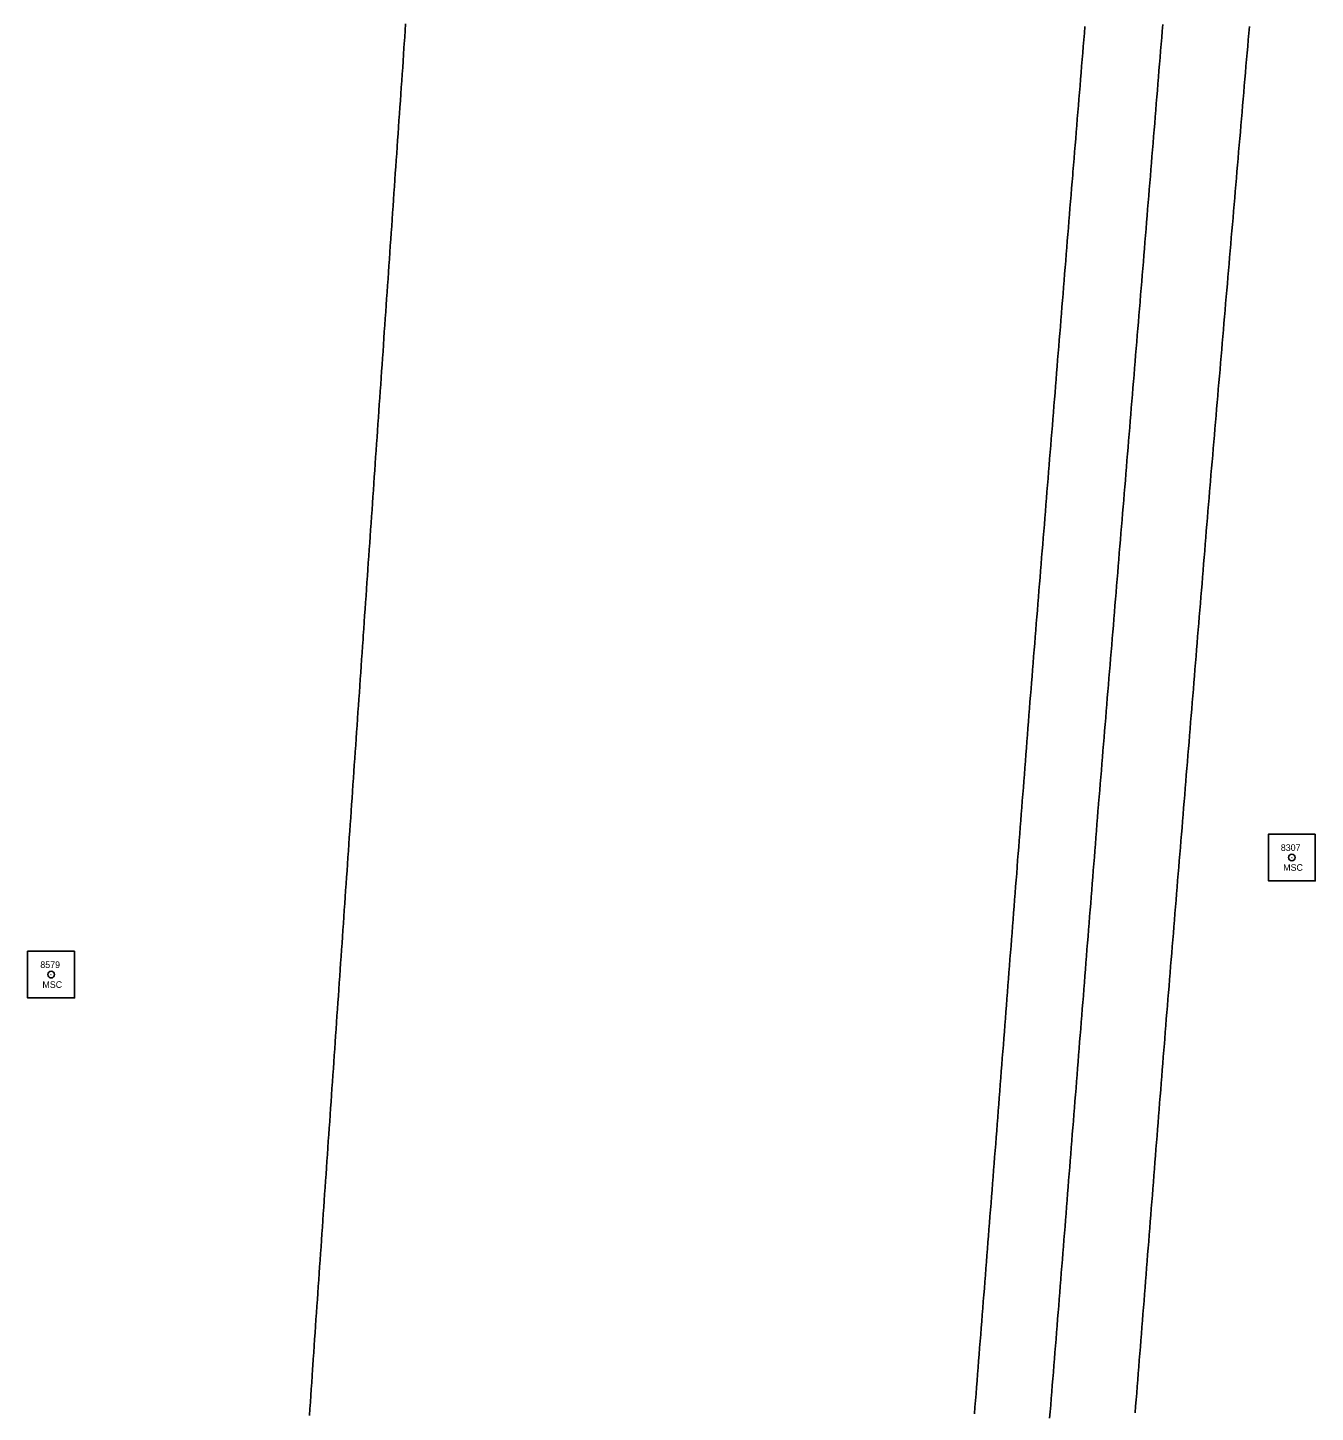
# Model space of a CAD drawing. Extents: x 205929 to 2357175, y -1785700 to 846739.
# Drawn here: x 2023477.3 to 2023671.7, y 810768.6 to 810977.7 of the extents above; entities that cross this region are included whole.
import ezdxf

# ---------------------------------------------------------------- set-up
doc = ezdxf.new("R2010")
doc.units = 0
for name, color, linetype in [('RD_HC_Survey', 7, 'Continuous'), ('RD_HC_txCode', 7, 'Continuous'), ('RD_Sketch1', 7, 'Continuous'), ('RD_SMD_Locator', 7, 'Continuous')]:
    doc.layers.add(name, color=color, linetype=linetype)

msp = doc.modelspace()

# ---------------------------------------------------------------- linework, layer by layer
at = {"layer": 'RD_HC_Survey'}
for points in [[(2023671.7, 810855.9), (2023664.63, 810855.9), (2023664.63, 810848.82), (2023671.7, 810848.82)], [(2023484.33, 810838.22), (2023477.25, 810838.22), (2023477.25, 810831.15), (2023484.33, 810831.15)]]:
    msp.add_lwpolyline(points, close=True, dxfattribs=at)
for centre in [(2023668.16, 810852.36), (2023480.79, 810834.68)]:
    msp.add_circle(centre, 0.5, dxfattribs=at)
at = {"layer": 'RD_Sketch1'}
for points in [[(2023534.31, 810978.27), (2023534.25, 810977.27), (2023534.19, 810976.28), (2023534.12, 810975.28), (2023534.08, 810974.65), (2023534.01, 810973.65), (2023533.95, 810972.66), (2023533.88, 810971.66), (2023533.81, 810970.66), (2023533.74, 810969.67), (2023533.67, 810968.67), (2023533.6, 810967.67), (2023533.53, 810966.67), (2023533.46, 810965.68), (2023533.39, 810964.68), (2023533.32, 810963.68), (2023533.25, 810962.69), (2023533.19, 810961.69), (2023533.19, 810961.69), (2023533.12, 810960.69), (2023533.05, 810959.7), (2023532.98, 810958.7), (2023532.91, 810957.7), (2023532.84, 810956.7), (2023532.77, 810955.71), (2023532.7, 810954.71), (2023532.63, 810953.71), (2023532.56, 810952.72), (2023532.49, 810951.72), (2023532.43, 810950.72), (2023532.36, 810949.73), (2023532.29, 810948.73), (2023532.22, 810947.73), (2023532.15, 810946.73), (2023532.08, 810945.74), (2023532.01, 810944.74), (2023531.94, 810943.74), (2023531.87, 810942.75), (2023531.8, 810941.75), (2023531.73, 810940.75), (2023531.67, 810939.75), (2023531.6, 810938.76), (2023531.53, 810937.76), (2023531.46, 810936.76), (2023531.39, 810935.77), (2023531.32, 810934.77), (2023531.25, 810933.77), (2023531.18, 810932.78), (2023531.11, 810931.78), (2023531.04, 810930.78), (2023530.97, 810929.78), (2023530.91, 810928.79), (2023530.84, 810927.79), (2023530.77, 810926.79), (2023530.7, 810925.8), (2023530.63, 810924.8), (2023530.56, 810923.8), (2023530.49, 810922.81), (2023530.42, 810921.81), (2023530.35, 810920.81), (2023530.28, 810919.81), (2023530.21, 810918.82), (2023530.15, 810917.82), (2023530.08, 810916.82), (2023530.01, 810915.83), (2023529.94, 810914.83), (2023529.87, 810913.83), (2023529.8, 810912.84), (2023529.73, 810911.84), (2023529.66, 810910.84), (2023529.59, 810909.84), (2023529.52, 810908.85), (2023529.45, 810907.85), (2023529.39, 810906.85), (2023529.32, 810905.86), (2023529.25, 810904.86), (2023529.18, 810903.86), (2023529.11, 810902.86), (2023529.04, 810901.87), (2023528.97, 810900.87), (2023528.9, 810899.87), (2023528.83, 810898.88), (2023528.76, 810897.88), (2023528.76, 810897.88), (2023528.69, 810896.88), (2023528.63, 810895.89), (2023528.56, 810894.89), (2023528.49, 810893.89), (2023528.42, 810892.89), (2023528.35, 810891.9), (2023528.28, 810890.9), (2023528.21, 810889.9), (2023528.14, 810888.91), (2023528.07, 810887.91), (2023528, 810886.91), (2023527.93, 810885.92), (2023527.89, 810885.27), (2023527.82, 810884.28), (2023527.75, 810883.28), (2023527.68, 810882.28), (2023527.61, 810881.29), (2023527.55, 810880.29), (2023527.48, 810879.29), (2023527.41, 810878.3), (2023527.34, 810877.3), (2023527.27, 810876.3), (2023527.2, 810875.31), (2023527.13, 810874.31), (2023527.06, 810873.31), (2023526.99, 810872.32), (2023526.93, 810871.32), (2023526.86, 810870.32), (2023526.79, 810869.32), (2023526.72, 810868.33), (2023526.65, 810867.33), (2023526.58, 810866.33), (2023526.51, 810865.34), (2023526.44, 810864.34), (2023526.37, 810863.34), (2023526.31, 810862.35), (2023526.24, 810861.35), (2023526.17, 810860.35), (2023526.1, 810859.36), (2023526.03, 810858.36), (2023525.96, 810857.36), (2023525.89, 810856.37), (2023525.82, 810855.37), (2023525.75, 810854.37), (2023525.68, 810853.37), (2023525.62, 810852.38), (2023525.55, 810851.38), (2023525.48, 810850.38), (2023525.41, 810849.39), (2023525.34, 810848.39), (2023525.27, 810847.39), (2023525.2, 810846.4), (2023525.13, 810845.4), (2023525.06, 810844.4), (2023525, 810843.41), (2023524.93, 810842.41), (2023524.86, 810841.41), (2023524.79, 810840.41), (2023524.72, 810839.42), (2023524.65, 810838.42), (2023524.58, 810837.42), (2023524.51, 810836.43), (2023524.44, 810835.43), (2023524.38, 810834.43), (2023524.38, 810834.43), (2023524.31, 810833.44), (2023524.24, 810832.44), (2023524.17, 810831.44), (2023524.1, 810830.45), (2023524.03, 810829.45), (2023523.96, 810828.45), (2023523.89, 810827.46), (2023523.82, 810826.46), (2023523.75, 810825.46), (2023523.69, 810824.46), (2023523.62, 810823.47), (2023523.55, 810822.47), (2023523.48, 810821.47), (2023523.41, 810820.48), (2023523.34, 810819.48), (2023523.27, 810818.48), (2023523.2, 810817.49), (2023523.13, 810816.49), (2023523.07, 810815.49), (2023523, 810814.5), (2023522.93, 810813.5), (2023522.86, 810812.5), (2023522.79, 810811.51), (2023522.72, 810810.51), (2023522.65, 810809.51), (2023522.58, 810808.51), (2023522.51, 810807.52), (2023522.45, 810806.52), (2023522.38, 810805.52), (2023522.31, 810804.53), (2023522.24, 810803.53), (2023522.17, 810802.53), (2023522.1, 810801.54), (2023522.03, 810800.54), (2023521.96, 810799.54), (2023521.89, 810798.55), (2023521.83, 810797.55), (2023521.76, 810796.55), (2023521.69, 810795.55), (2023521.62, 810794.56), (2023521.55, 810793.56), (2023521.48, 810792.56), (2023521.41, 810791.57), (2023521.34, 810790.57), (2023521.27, 810789.57), (2023521.2, 810788.58), (2023521.14, 810787.58), (2023521.07, 810786.58), (2023521, 810785.59), (2023520.93, 810784.59), (2023520.86, 810783.59), (2023520.79, 810782.6), (2023520.72, 810781.6), (2023520.65, 810780.6), (2023520.58, 810779.6), (2023520.52, 810778.61), (2023520.45, 810777.61), (2023520.38, 810776.61), (2023520.31, 810775.62), (2023520.27, 810775.09), (2023520.2, 810774.09), (2023520.14, 810773.09), (2023520.07, 810772.09), (2023520, 810771.1), (2023520, 810771.1), (2023519.94, 810770.1), (2023519.87, 810769.1), (2023519.8, 810768.11)], [(2023636.91, 810977.87), (2023636.83, 810976.87), (2023636.74, 810975.88), (2023636.66, 810974.88), (2023636.58, 810973.88), (2023636.5, 810972.89), (2023636.41, 810971.89), (2023636.33, 810970.9), (2023636.25, 810969.9), (2023636.17, 810968.9), (2023636.09, 810967.91), (2023636, 810966.91), (2023635.92, 810965.92), (2023635.84, 810964.92), (2023635.76, 810963.92), (2023635.67, 810962.93), (2023635.59, 810961.93), (2023635.51, 810960.93), (2023635.43, 810959.94), (2023635.34, 810958.94), (2023635.26, 810957.95), (2023635.18, 810956.95), (2023635.1, 810955.95), (2023635.06, 810955.44), (2023634.97, 810954.44), (2023634.89, 810953.45), (2023634.81, 810952.45), (2023634.73, 810951.45), (2023634.65, 810950.46), (2023634.65, 810950.46), (2023634.57, 810949.46), (2023634.49, 810948.46), (2023634.41, 810947.47), (2023634.33, 810946.47), (2023634.25, 810945.48), (2023634.17, 810944.48), (2023634.09, 810943.48), (2023634.01, 810942.49), (2023633.92, 810941.49), (2023633.84, 810940.5), (2023633.76, 810939.5), (2023633.68, 810938.5), (2023633.6, 810937.51), (2023633.52, 810936.51), (2023633.44, 810935.52), (2023633.36, 810934.52), (2023633.28, 810933.52), (2023633.2, 810932.53), (2023633.12, 810931.53), (2023633.04, 810930.53), (2023632.96, 810929.54), (2023632.87, 810928.54), (2023632.79, 810927.55), (2023632.71, 810926.55), (2023632.63, 810925.55), (2023632.55, 810924.56), (2023632.47, 810923.56), (2023632.39, 810922.57), (2023632.31, 810921.57), (2023632.23, 810920.57), (2023632.15, 810919.58), (2023632.07, 810918.58), (2023631.99, 810917.59), (2023631.91, 810916.59), (2023631.83, 810915.59), (2023631.74, 810914.6), (2023631.66, 810913.6), (2023631.58, 810912.6), (2023631.5, 810911.61), (2023631.42, 810910.61), (2023631.34, 810909.62), (2023631.26, 810908.62), (2023631.18, 810907.62), (2023631.1, 810906.63), (2023631.02, 810905.63), (2023630.94, 810904.64), (2023630.86, 810903.64), (2023630.78, 810902.64), (2023630.69, 810901.65), (2023630.61, 810900.65), (2023630.53, 810899.65), (2023630.45, 810898.66), (2023630.37, 810897.66), (2023630.29, 810896.67), (2023630.21, 810895.67), (2023630.13, 810894.67), (2023630.05, 810893.68), (2023629.97, 810892.68), (2023629.89, 810891.69), (2023629.81, 810890.69), (2023629.73, 810889.69), (2023629.64, 810888.7), (2023629.56, 810887.7), (2023629.48, 810886.71), (2023629.48, 810886.71), (2023629.4, 810885.71), (2023629.32, 810884.71), (2023629.24, 810883.72), (2023629.16, 810882.72), (2023629.08, 810881.72), (2023629, 810880.73), (2023628.92, 810879.73), (2023628.84, 810878.74), (2023628.77, 810877.86), (2023628.69, 810876.86), (2023628.61, 810875.87), (2023628.53, 810874.87), (2023628.46, 810873.87), (2023628.38, 810872.88), (2023628.3, 810871.88), (2023628.22, 810870.89), (2023628.15, 810869.89), (2023628.07, 810868.89), (2023627.99, 810867.9), (2023627.91, 810866.9), (2023627.84, 810865.91), (2023627.76, 810864.91), (2023627.68, 810863.91), (2023627.61, 810862.92), (2023627.53, 810861.92), (2023627.45, 810860.92), (2023627.37, 810859.93), (2023627.3, 810858.93), (2023627.22, 810857.94), (2023627.14, 810856.94), (2023627.06, 810855.94), (2023626.99, 810854.95), (2023626.91, 810853.95), (2023626.83, 810852.95), (2023626.75, 810851.96), (2023626.68, 810850.96), (2023626.6, 810849.97), (2023626.52, 810848.97), (2023626.44, 810847.97), (2023626.37, 810846.98), (2023626.29, 810845.98), (2023626.21, 810844.98), (2023626.13, 810843.99), (2023626.06, 810842.99), (2023625.98, 810842), (2023625.9, 810841), (2023625.82, 810840), (2023625.75, 810839.01), (2023625.67, 810838.01), (2023625.59, 810837.01), (2023625.52, 810836.02), (2023625.44, 810835.02), (2023625.36, 810834.03), (2023625.28, 810833.03), (2023625.21, 810832.03), (2023625.13, 810831.04), (2023625.05, 810830.04), (2023624.97, 810829.05), (2023624.9, 810828.05), (2023624.82, 810827.05), (2023624.74, 810826.06), (2023624.66, 810825.06), (2023624.59, 810824.06), (2023624.51, 810823.07), (2023624.51, 810823.07), (2023624.43, 810822.07), (2023624.35, 810821.08), (2023624.28, 810820.08), (2023624.2, 810819.08), (2023624.12, 810818.09), (2023624.04, 810817.09), (2023623.97, 810816.09), (2023623.89, 810815.1), (2023623.81, 810814.1), (2023623.74, 810813.11), (2023623.66, 810812.11), (2023623.58, 810811.11), (2023623.5, 810810.12), (2023623.43, 810809.12), (2023623.35, 810808.12), (2023623.27, 810807.13), (2023623.19, 810806.13), (2023623.12, 810805.14), (2023623.04, 810804.14), (2023622.96, 810803.14), (2023622.88, 810802.15), (2023622.81, 810801.15), (2023622.73, 810800.16), (2023622.65, 810799.16), (2023622.57, 810798.16), (2023622.5, 810797.17), (2023622.42, 810796.17), (2023622.34, 810795.17), (2023622.27, 810794.27), (2023622.19, 810793.27), (2023622.11, 810792.27), (2023622.03, 810791.28), (2023621.96, 810790.28), (2023621.88, 810789.29), (2023621.8, 810788.29), (2023621.72, 810787.29), (2023621.64, 810786.3), (2023621.56, 810785.3), (2023621.48, 810784.3), (2023621.4, 810783.31), (2023621.32, 810782.31), (2023621.25, 810781.31), (2023621.17, 810780.32), (2023621.09, 810779.32), (2023621.01, 810778.33), (2023620.93, 810777.33), (2023620.85, 810776.33), (2023620.77, 810775.34), (2023620.69, 810774.34), (2023620.61, 810773.34), (2023620.53, 810772.35), (2023620.46, 810771.35), (2023620.38, 810770.36), (2023620.3, 810769.36), (2023620.22, 810768.36)], [(2023648.66, 810978.19), (2023648.58, 810977.19), (2023648.5, 810976.2), (2023648.42, 810975.2), (2023648.34, 810974.2), (2023648.25, 810973.21), (2023648.17, 810972.21), (2023648.09, 810971.21), (2023648.01, 810970.22), (2023647.93, 810969.22), (2023647.85, 810968.23), (2023647.77, 810967.23), (2023647.68, 810966.23), (2023647.6, 810965.24), (2023647.52, 810964.24), (2023647.44, 810963.25), (2023647.44, 810963.25), (2023647.36, 810962.25), (2023647.28, 810961.25), (2023647.2, 810960.26), (2023647.11, 810959.26), (2023647.03, 810958.26), (2023646.95, 810957.27), (2023646.87, 810956.27), (2023646.79, 810955.28), (2023646.71, 810954.28), (2023646.63, 810953.28), (2023646.54, 810952.29), (2023646.46, 810951.29), (2023646.38, 810950.3), (2023646.3, 810949.3), (2023646.22, 810948.3), (2023646.14, 810947.31), (2023646.06, 810946.31), (2023645.97, 810945.32), (2023645.89, 810944.32), (2023645.81, 810943.32), (2023645.73, 810942.33), (2023645.65, 810941.33), (2023645.57, 810940.33), (2023645.49, 810939.34), (2023645.4, 810938.34), (2023645.32, 810937.35), (2023645.24, 810936.35), (2023645.23, 810936.22), (2023645.15, 810935.23), (2023645.07, 810934.23), (2023644.98, 810933.24), (2023644.9, 810932.24), (2023644.82, 810931.24), (2023644.74, 810930.25), (2023644.66, 810929.25), (2023644.57, 810928.26), (2023644.49, 810927.26), (2023644.41, 810926.26), (2023644.33, 810925.27), (2023644.24, 810924.27), (2023644.16, 810923.28), (2023644.08, 810922.28), (2023644, 810921.29), (2023643.91, 810920.29), (2023643.83, 810919.29), (2023643.75, 810918.3), (2023643.67, 810917.3), (2023643.59, 810916.31), (2023643.5, 810915.31), (2023643.42, 810914.31), (2023643.34, 810913.32), (2023643.26, 810912.32), (2023643.17, 810911.33), (2023643.09, 810910.33), (2023643.01, 810909.33), (2023642.93, 810908.34), (2023642.84, 810907.34), (2023642.76, 810906.35), (2023642.68, 810905.35), (2023642.6, 810904.35), (2023642.52, 810903.36), (2023642.43, 810902.36), (2023642.35, 810901.37), (2023642.27, 810900.37), (2023642.27, 810900.37), (2023642.19, 810899.37), (2023642.1, 810898.38), (2023642.02, 810897.38), (2023641.94, 810896.39), (2023641.86, 810895.39), (2023641.77, 810894.4), (2023641.69, 810893.4), (2023641.61, 810892.4), (2023641.53, 810891.41), (2023641.44, 810890.41), (2023641.36, 810889.42), (2023641.28, 810888.42), (2023641.2, 810887.42), (2023641.12, 810886.43), (2023641.03, 810885.43), (2023640.95, 810884.44), (2023640.87, 810883.44), (2023640.79, 810882.44), (2023640.7, 810881.45), (2023640.62, 810880.45), (2023640.54, 810879.46), (2023640.46, 810878.46), (2023640.37, 810877.46), (2023640.29, 810876.47), (2023640.21, 810875.47), (2023640.13, 810874.48), (2023640.05, 810873.48), (2023639.96, 810872.48), (2023639.88, 810871.49), (2023639.8, 810870.49), (2023639.72, 810869.5), (2023639.63, 810868.5), (2023639.55, 810867.5), (2023639.47, 810866.51), (2023639.39, 810865.51), (2023639.3, 810864.52), (2023639.22, 810863.52), (2023639.14, 810862.53), (2023639.06, 810861.53), (2023638.98, 810860.53), (2023638.96, 810860.38), (2023638.88, 810859.38), (2023638.8, 810858.39), (2023638.73, 810857.39), (2023638.65, 810856.39), (2023638.57, 810855.4), (2023638.49, 810854.4), (2023638.41, 810853.4), (2023638.33, 810852.41), (2023638.25, 810851.41), (2023638.17, 810850.42), (2023638.09, 810849.42), (2023638.01, 810848.42), (2023637.93, 810847.43), (2023637.85, 810846.43), (2023637.78, 810845.43), (2023637.7, 810844.44), (2023637.62, 810843.44), (2023637.54, 810842.45), (2023637.46, 810841.45), (2023637.38, 810840.45), (2023637.3, 810839.46), (2023637.22, 810838.46), (2023637.14, 810837.46), (2023637.14, 810837.46), (2023637.06, 810836.47), (2023636.98, 810835.47), (2023636.9, 810834.48), (2023636.82, 810833.48), (2023636.75, 810832.48), (2023636.67, 810831.49), (2023636.59, 810830.49), (2023636.51, 810829.49), (2023636.43, 810828.5), (2023636.35, 810827.5), (2023636.27, 810826.51), (2023636.19, 810825.51), (2023636.11, 810824.51), (2023636.03, 810823.52), (2023635.95, 810822.52), (2023635.87, 810821.52), (2023635.8, 810820.53), (2023635.72, 810819.53), (2023635.64, 810818.54), (2023635.56, 810817.54), (2023635.48, 810816.54), (2023635.4, 810815.55), (2023635.32, 810814.55), (2023635.24, 810813.55), (2023635.16, 810812.56), (2023635.08, 810811.56), (2023635, 810810.57), (2023634.92, 810809.57), (2023634.85, 810808.57), (2023634.77, 810807.58), (2023634.69, 810806.58), (2023634.61, 810805.59), (2023634.53, 810804.59), (2023634.45, 810803.59), (2023634.37, 810802.6), (2023634.29, 810801.6), (2023634.21, 810800.6), (2023634.13, 810799.61), (2023634.05, 810798.61), (2023633.97, 810797.62), (2023633.9, 810796.62), (2023633.82, 810795.62), (2023633.74, 810794.63), (2023633.66, 810793.63), (2023633.58, 810792.63), (2023633.5, 810791.64), (2023633.42, 810790.64), (2023633.34, 810789.65), (2023633.26, 810788.65), (2023633.18, 810787.65), (2023633.1, 810786.66), (2023633.02, 810785.66), (2023632.95, 810784.66), (2023632.87, 810783.67), (2023632.79, 810782.67), (2023632.7, 810781.62), (2023632.62, 810780.62), (2023632.54, 810779.63), (2023632.46, 810778.63), (2023632.38, 810777.63), (2023632.3, 810776.64), (2023632.22, 810775.64), (2023632.14, 810774.65), (2023632.06, 810773.65), (2023632.06, 810773.65), (2023631.98, 810772.65), (2023631.9, 810771.66), (2023631.82, 810770.66), (2023631.74, 810769.66), (2023631.66, 810768.67), (2023631.58, 810767.67)], [(2023661.75, 810977.87), (2023661.66, 810976.87), (2023661.57, 810975.87), (2023661.49, 810974.88), (2023661.4, 810973.88), (2023661.32, 810972.89), (2023661.23, 810971.89), (2023661.15, 810970.89), (2023661.06, 810969.9), (2023660.98, 810968.9), (2023660.89, 810967.91), (2023660.81, 810966.91), (2023660.72, 810965.92), (2023660.64, 810964.92), (2023660.55, 810963.92), (2023660.46, 810962.93), (2023660.38, 810961.93), (2023660.29, 810960.94), (2023660.21, 810959.94), (2023660.12, 810958.95), (2023660.04, 810957.95), (2023659.95, 810956.95), (2023659.87, 810955.96), (2023659.78, 810954.96), (2023659.7, 810953.97), (2023659.61, 810952.97), (2023659.53, 810951.98), (2023659.44, 810950.98), (2023659.36, 810949.98), (2023659.27, 810948.99), (2023659.18, 810947.99), (2023659.1, 810947), (2023659.01, 810946), (2023658.93, 810945.01), (2023658.84, 810944.01), (2023658.76, 810943.01), (2023658.67, 810942.02), (2023658.67, 810942.02), (2023658.59, 810941.02), (2023658.5, 810940.03), (2023658.42, 810939.03), (2023658.33, 810938.04), (2023658.25, 810937.04), (2023658.16, 810936.04), (2023658.07, 810935.05), (2023657.99, 810934.05), (2023657.9, 810933.06), (2023657.82, 810932.06), (2023657.73, 810931.07), (2023657.65, 810930.07), (2023657.56, 810929.07), (2023657.48, 810928.08), (2023657.39, 810927.08), (2023657.31, 810926.09), (2023657.22, 810925.09), (2023657.14, 810924.1), (2023657.05, 810923.1), (2023656.96, 810922.1), (2023656.88, 810921.11), (2023656.79, 810920.11), (2023656.71, 810919.12), (2023656.62, 810918.12), (2023656.54, 810917.13), (2023656.45, 810916.13), (2023656.37, 810915.13), (2023656.28, 810914.14), (2023656.2, 810913.14), (2023656.11, 810912.15), (2023656.03, 810911.15), (2023655.94, 810910.16), (2023655.85, 810909.16), (2023655.81, 810908.66), (2023655.73, 810907.66), (2023655.65, 810906.67), (2023655.57, 810905.67), (2023655.49, 810904.67), (2023655.4, 810903.68), (2023655.32, 810902.68), (2023655.24, 810901.69), (2023655.16, 810900.69), (2023655.08, 810899.69), (2023655, 810898.7), (2023654.91, 810897.7), (2023654.83, 810896.71), (2023654.75, 810895.71), (2023654.67, 810894.71), (2023654.59, 810893.72), (2023654.51, 810892.72), (2023654.42, 810891.73), (2023654.34, 810890.73), (2023654.26, 810889.73), (2023654.18, 810888.74), (2023654.1, 810887.74), (2023654.02, 810886.74), (2023653.93, 810885.75), (2023653.85, 810884.75), (2023653.77, 810883.76), (2023653.69, 810882.76), (2023653.61, 810881.76), (2023653.53, 810880.77), (2023653.44, 810879.77), (2023653.36, 810878.78), (2023653.36, 810878.78), (2023653.28, 810877.78), (2023653.2, 810876.78), (2023653.12, 810875.79), (2023653.04, 810874.79), (2023652.96, 810873.8), (2023652.87, 810872.8), (2023652.79, 810871.8), (2023652.71, 810870.81), (2023652.63, 810869.81), (2023652.55, 810868.82), (2023652.47, 810867.82), (2023652.38, 810866.82), (2023652.3, 810865.83), (2023652.22, 810864.83), (2023652.14, 810863.83), (2023652.06, 810862.84), (2023651.98, 810861.84), (2023651.89, 810860.85), (2023651.81, 810859.85), (2023651.73, 810858.85), (2023651.65, 810857.86), (2023651.57, 810856.86), (2023651.49, 810855.87), (2023651.4, 810854.87), (2023651.32, 810853.87), (2023651.24, 810852.88), (2023651.16, 810851.88), (2023651.08, 810850.89), (2023651, 810849.89), (2023650.91, 810848.89), (2023650.83, 810847.9), (2023650.75, 810846.9), (2023650.67, 810845.91), (2023650.59, 810844.91), (2023650.51, 810843.91), (2023650.43, 810842.92), (2023650.34, 810841.92), (2023650.26, 810840.92), (2023650.18, 810839.93), (2023650.1, 810838.93), (2023650.02, 810837.94), (2023649.94, 810836.94), (2023649.85, 810835.94), (2023649.77, 810834.95), (2023649.69, 810833.95), (2023649.61, 810832.96), (2023649.53, 810831.96), (2023649.45, 810830.96), (2023649.36, 810829.97), (2023649.28, 810828.97), (2023649.2, 810827.98), (2023649.12, 810826.98), (2023649.04, 810825.98), (2023648.96, 810824.99), (2023648.9, 810824.27), (2023648.82, 810823.28), (2023648.74, 810822.28), (2023648.66, 810821.28), (2023648.58, 810820.29), (2023648.5, 810819.29), (2023648.43, 810818.29), (2023648.35, 810817.3), (2023648.27, 810816.3), (2023648.19, 810815.31), (2023648.19, 810815.31), (2023648.11, 810814.31), (2023648.03, 810813.31), (2023647.95, 810812.32), (2023647.88, 810811.32), (2023647.8, 810810.32), (2023647.72, 810809.33), (2023647.64, 810808.33), (2023647.56, 810807.33), (2023647.48, 810806.34), (2023647.4, 810805.34), (2023647.33, 810804.35), (2023647.25, 810803.35), (2023647.17, 810802.35), (2023647.09, 810801.36), (2023647.01, 810800.36), (2023646.93, 810799.36), (2023646.85, 810798.37), (2023646.78, 810797.37), (2023646.7, 810796.38), (2023646.62, 810795.38), (2023646.54, 810794.38), (2023646.46, 810793.39), (2023646.38, 810792.39), (2023646.3, 810791.39), (2023646.23, 810790.4), (2023646.15, 810789.4), (2023646.07, 810788.4), (2023645.99, 810787.41), (2023645.91, 810786.41), (2023645.83, 810785.42), (2023645.75, 810784.42), (2023645.67, 810783.42), (2023645.6, 810782.43), (2023645.52, 810781.43), (2023645.44, 810780.43), (2023645.36, 810779.44), (2023645.28, 810778.44), (2023645.2, 810777.45), (2023645.12, 810776.45), (2023645.05, 810775.45), (2023644.97, 810774.46), (2023644.89, 810773.46), (2023644.81, 810772.46), (2023644.73, 810771.47), (2023644.65, 810770.47), (2023644.57, 810769.48), (2023644.5, 810768.48)]]:
    msp.add_lwpolyline(points, dxfattribs=at)
at = {"layer": 'RD_SMD_Locator'}
for centre in [(2023668.16, 810852.36), (2023480.79, 810834.68)]:
    msp.add_circle(centre, 0.001, dxfattribs=at)

# ---------------------------------------------------------------- texts
at = {"layer": 'RD_HC_txCode'}
for s, p in [('8307', (2023666.49, 810853.36)), ('MSC', (2023666.85, 810850.36)), ('8579', (2023479.16, 810835.68)), ('MSC', (2023479.48, 810832.68))]:
    msp.add_text(s, height=1, dxfattribs=at).set_placement(p)

doc.saveas('drawing.dxf')
